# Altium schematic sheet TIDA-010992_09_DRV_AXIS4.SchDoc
size 431 x 279 mm; Date: Not shown in title block; ApprovedBy: Not shown in title block; CheckedBy: Not shown in title block; Author: Not shown in title block; CompanyName: Not shown in title block; Engineer: Not shown in title block; Organization: Not shown in title block; Address1: Not shown in title block; Address2: Not shown in title block; Address3: Not shown in title block; Address4: Not shown in title block; DocumentNumber: 9; Revision: Use project parameter SCH_Rev; SheetNumber: 9; SheetTotal: 13; PageSetup: Record=PageOptions¦CenterHorizontal=True¦CenterVertical=True¦PrintScale=1.00¦XCorrection=1.00¦YCorrection=1.00¦PrintKind=0¦BorderSize=5000000¦LeftOffset=0¦BottomOffset=0¦Orientation=2¦PaperLength=1000¦PaperWidth=1000¦Scale=100¦PaperSource=15¦PrintQuality=600¦MediaType=1¦DitherType=10¦PaperKind=Letter¦PrintScaleMode=1
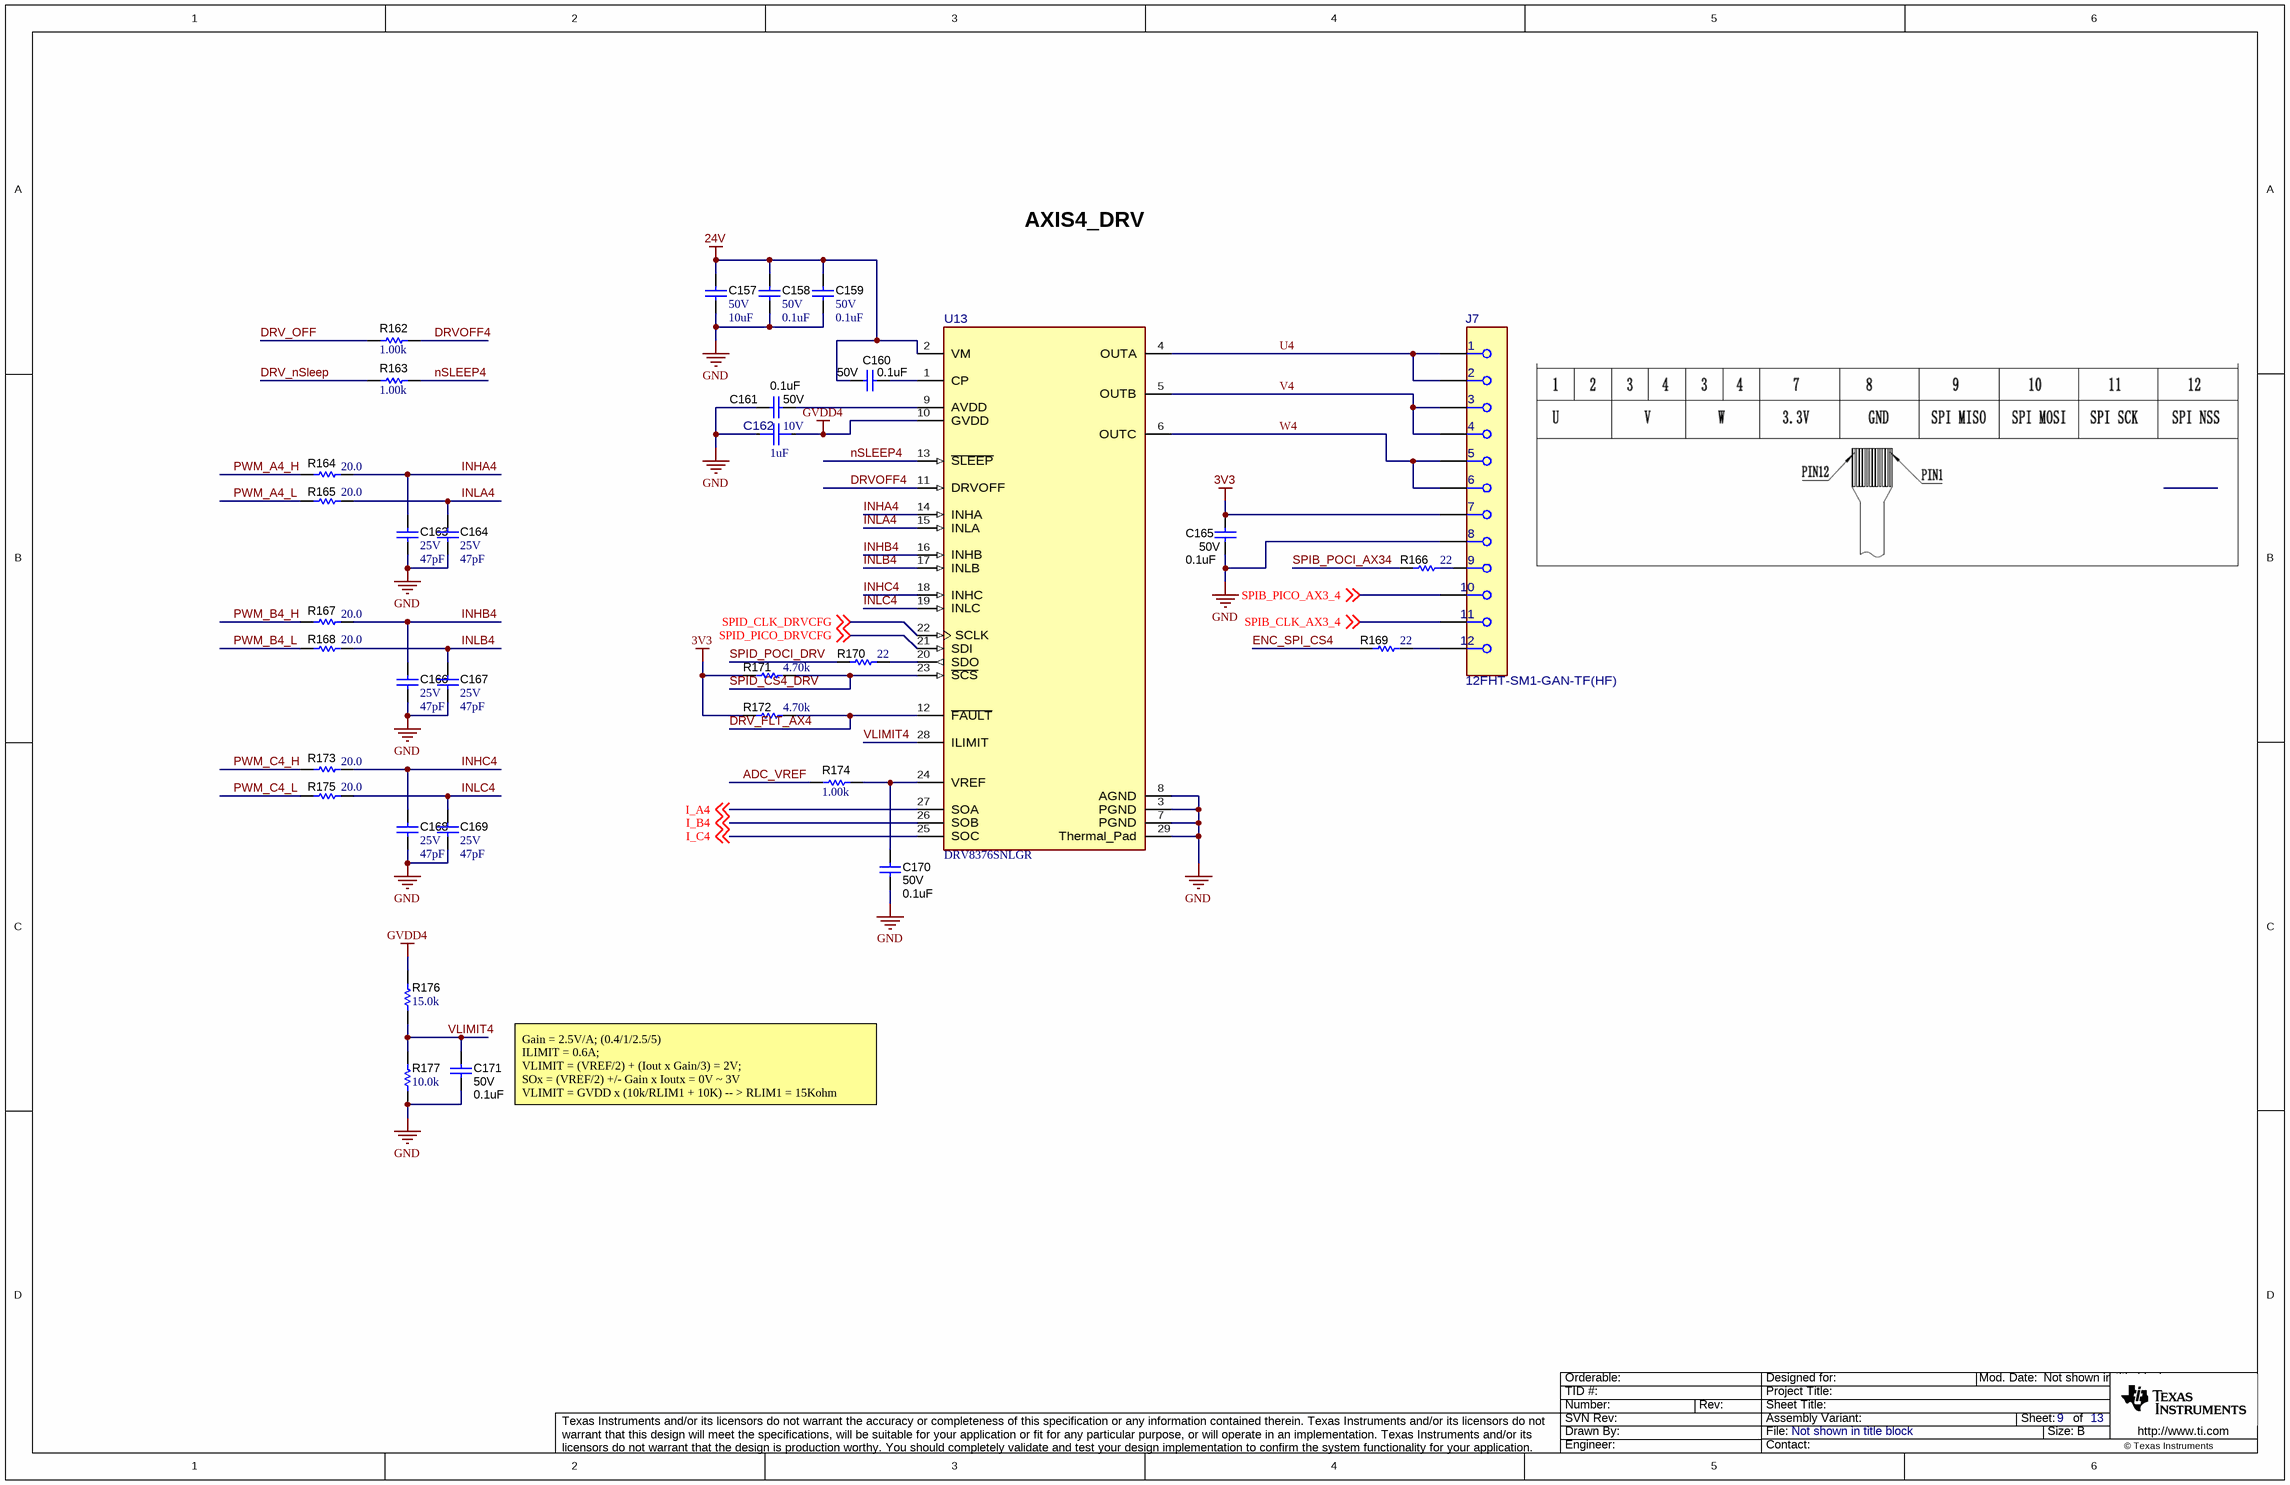
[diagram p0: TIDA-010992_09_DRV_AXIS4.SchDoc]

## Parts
C157  VDC_V: 50V  ValueDisplayed: 10uF  [1206_180]  (hidden comment: CL31B106KBHNNNE)
C158  VDC_V: 50V  ValueDisplayed: 0.1uF  [0402]  (hidden comment: C1005X7R1H104K050BE)
C159  VDC_V: 50V  ValueDisplayed: 0.1uF  [0402]  (hidden comment: C1005X7R1H104K050BE)
C160  VDC_V: 50V  ValueDisplayed: 0.1uF  [0402]  (hidden comment: CGA2B3X7R1H104M050BB)
C161  VDC_V: 50V  ValueDisplayed: 0.1uF  [0402]  (hidden comment: CGA2B3X7R1H104M050BB)
C162  VDC_V: 10V  ValueDisplayed: 1uF  [FP-GMC04X7R105K10NT_0402-MFG]  (hidden comment: GMC04X7R105K10NT)
C163  VDC_V: 25V  ValueDisplayed: 47pF  [0201_033]  (hidden comment: GRM0335C1E470JA01D)
C164  VDC_V: 25V  ValueDisplayed: 47pF  [0201_033]  (hidden comment: GRM0335C1E470JA01D)
C165  VDC_V: 50V  ValueDisplayed: 0.1uF  [0402]  (hidden comment: CGA2B3X7R1H104M050BB)
C166  VDC_V: 25V  ValueDisplayed: 47pF  [0201_033]  (hidden comment: GRM0335C1E470JA01D)
C167  VDC_V: 25V  ValueDisplayed: 47pF  [0201_033]  (hidden comment: GRM0335C1E470JA01D)
C168  VDC_V: 25V  ValueDisplayed: 47pF  [0201_033]  (hidden comment: GRM0335C1E470JA01D)
C169  VDC_V: 25V  ValueDisplayed: 47pF  [0201_033]  (hidden comment: GRM0335C1E470JA01D)
C170  VDC_V: 50V  ValueDisplayed: 0.1uF  [0402]  (hidden comment: CGA2B3X7R1H104M050BB)
C171  VDC_V: 50V  ValueDisplayed: 0.1uF  [0402]  (hidden comment: CGA2B3X7R1H104M050BB)
J7  12FHT-SM1-GAN-TF(HF)  [FP-12FHT-SM1-GAN-TF(HF)_CONN_FPC_12-MFG]
R162  ValueDisplayed: 1.00k  [0402]  (hidden comment: CRCW04021K00FKED)
R163  ValueDisplayed: 1.00k  [0402]  (hidden comment: CRCW04021K00FKED)
R164  ValueDisplayed: 20.0  [0201_033]  (hidden comment: CRCW020120R0FNED)
R165  ValueDisplayed: 20.0  [0201_033]  (hidden comment: CRCW020120R0FNED)
R166  ValueDisplayed: 22  [0201]  (hidden comment: ERJ-1GNJ220C)
R167  ValueDisplayed: 20.0  [0201_033]  (hidden comment: CRCW020120R0FNED)
R168  ValueDisplayed: 20.0  [0201_033]  (hidden comment: CRCW020120R0FNED)
R169  ValueDisplayed: 22  [0201]  (hidden comment: ERJ-1GNJ220C)
R170  ValueDisplayed: 22  [0201]  (hidden comment: ERJ-1GNJ220C)
R171  ValueDisplayed: 4.70k  [0201]  (hidden comment: RC0201FR-7D4K7L)
R172  ValueDisplayed: 4.70k  [0201]  (hidden comment: RC0201FR-7D4K7L)
R173  ValueDisplayed: 20.0  [0201_033]  (hidden comment: CRCW020120R0FNED)
R174  ValueDisplayed: 1.00k  [0402]  (hidden comment: CRCW04021K00FKED)
R175  ValueDisplayed: 20.0  [0201_033]  (hidden comment: CRCW020120R0FNED)
R176  ValueDisplayed: 15.0k  [0402]  (hidden comment: RC0402FR-0715KL)
R177  ValueDisplayed: 10.0k  [0402L]  (hidden comment: CRCW040210K0FKED)
U13  DRV8376SNLGR  [NLG0028A-MFG]

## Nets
3V3: C165.2 J7.7 R171.2 R172.2
24V: C157.1 C158.1 C159.1 C160.1 U13.2(VM)
GND: C157.2 C158.2 C159.2 C161.1 C162.1 C163.2 C164.2 C165.1 C166.2 C167.2 C168.2 C169.2 C170.1 C171.1 J7.8 R177.1 U13.3(PGND) U13.7(PGND) U13.8(AGND) U13.29(Thermal_Pad)
GVDD4: C162.2 R176.2 U13.10(GVDD)
ADC_VREF: R174.1
DRV_FLT_AX4: R172.1 U13.12(~{FAULT})
DRV_nSleep: R163.1
DRV_OFF: R162.1
DRVOFF4: R162.2 U13.11(DRVOFF)
ENC_SPI_CS4: R169.1
I_A4: U13.27(SOA) ; off-sheet I_A4
I_B4: U13.26(SOB) ; off-sheet I_B4
I_C4: U13.25(SOC) ; off-sheet I_C4
INHA4: C163.1 R164.2 U13.14(INHA)
INHB4: C166.1 R167.2 U13.16(INHB)
INHC4: C168.1 R173.2 U13.18(INHC)
INLA4: C164.1 R165.2 U13.15(INLA)
INLB4: C167.1 R168.2 U13.17(INLB)
INLC4: C169.1 R175.2 U13.19(INLC)
nSLEEP4: R163.2 U13.13(~{SLEEP})
PWM_A4_H: R164.1
PWM_A4_L: R165.1
PWM_B4_H: R167.1
PWM_B4_L: R168.1
PWM_C4_H: R173.1
PWM_C4_L: R175.1
SPIB_CLK_AX3_4: J7.11 ; off-sheet SPIB_CLK_AX3_4
SPIB_PICO_AX3_4: J7.10 ; off-sheet SPIB_PICO_AX3_4
SPIB_POCI_AX34: R166.1
SPID_CLK_DRVCFG: U13.22(SCLK) ; off-sheet SPID_CLK_DRVCFG
SPID_CS4_DRV: R171.1 U13.23(~{SCS})
SPID_PICO_DRVCFG: U13.21(SDI) ; off-sheet SPID_PICO_DRVCFG
SPID_POCI_DRV: R170.1
U4: J7.1 J7.2 U13.4(OUTA)
V4: J7.3 J7.4 U13.5(OUTB)
VLIMIT4: C171.2 R176.1 R177.2 U13.28(ILIMIT)
W4: J7.5 J7.6 U13.6(OUTC)
NetC160_2: C160.2 U13.1(CP)
NetC161_2: C161.2 U13.9(AVDD)
NetC170_2: C170.2 R174.2 U13.24(VREF)
NetJ7_9: J7.9 R166.2
NetJ7_12: J7.12 R169.2
NetR170_2: R170.2 U13.20(SDO)

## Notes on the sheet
- AXIS4_DRV
- Gain = 2.5V/A; (0.4/1/2.5/5)
  ILIMIT = 0.6A;
  VLIMIT = (VREF/2) + (Iout x Gain/3) = 2V;
  SOx = (VREF/2) +/- Gain x Ioutx = 0V ~ 3V
  VLIMIT = GVDD x (10k/RLIM1 + 10K) -- > RLIM1 = 15Kohm

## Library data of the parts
C157 = CMP-0008802-2: CAP, CERM, 10 uF, 50 V, +/- 10%, X7R, 1206; Manufacturer: Samsung; TaMin_C: -55°C; Polarized: N; SizeAreaWB_mm2: 10.92; Value1: Unknown; U/M: EA; Value: 10uF; TaMax_C: 125°C; SizeZ_mm: 1.8; SizeX_mm: 3.2; SizeY_mm: 1.6; Cap_Case: 1206; SizeArea_mm2: 5.12; Cap_F: 10µF; AEC Category: Q200
C158 C159 = CMP-0064946-2: CAP, CERM, 0.1 uF, 50 V,+/- 10%, X7R, 0402; Manufacturer: TDK; TaMin_C: -55°C; Polarized: N; SizeAreaWB_mm2: 3; Value1: Unknown; U/M: EA; Value: 0.1uF; TaMax_C: 125°C; SizeZ_mm: 0.6; SizeX_mm: 1; SizeY_mm: 0.5; Cap_F: 100nF; AEC Category: Q200
C160 C161 C165 C170 C171 = CMP-0006326-2: CAP, CERM, 0.1 uF, 50 V, +/- 20%, X7R, AEC-Q200 Grade 1, 0402; Manufacturer: TDK; TaMin_C: -55°C; Polarized: N; SizeAreaWB_mm2: 3; Value1: Unknown; U/M: EA; Value: 0.1uF; TaMax_C: 125°C; SizeZ_mm: 0.6; SizeX_mm: 1; SizeY_mm: 0.5; AEC Qualified: Y; Cap_F: 100nF; AEC Category: Q200
C162 = CMP-0093200-1: 1µF ±10% 10V Ceramic Capacitor X7R 0402 (1005 Metric); Manufacturer: Cal-Chip Electronics; TempCo: 15%; SizeZ_mm: 0.6mm; AEC Qualified: No
C163 C164 C166-C169 = CMP-0009662-3: CAP, CERM, 47 pF, 25 V, +/- 5%, C0G/NP0, 0201; Manufacturer: MuRata; TaMin_C: -55°C; Polarized: N; SizeAreaWB_mm2: 2.08; Value1: Unknown; U/M: EA; Value: 47pF; TaMax_C: 125°C; SizeZ_mm: 0.33; SizeX_mm: 0.6; SizeY_mm: 0.3; Cap_Case: 0201; SizeArea_mm2: 0.18; AEC Category: Q200
J7 = CMP-0126588-1: Conn FPC Connector F 12 POS 0.5mm Solder Ver SMD T/R; Manufacturer: JST; ContactFinish: Gold,Nickel; Current_A: 500mA; Voltage_V: 50V; AEC Qualified: No; Conn Gender: Female; Conn Orientation: Vertical; Is Female: yes; SizeZ_mm: 3.3mm; Standoff Height: 0.13mm
R162 R163 R174 = CMP-0026071-3: RES, 1.00 k, 1%, 0.063 W, AEC-Q200 Grade 0, 0402; Manufacturer: Vishay-Dale; Power_W: 63mW; TempCo: 100 ppm/C; Value_Code: 1k00; Value: 1.00k; EIA_Code: E96; Res_ohm: 1k; SizeX_mm: 1; SizeY_mm: 0.5; SizeZ_mm: 0.6; Value2: 0.063W; AEC Qualified: Y; VDC_V: 50V; AEC Category: Q200; AEC Grade: 0
R164 R165 R167 R168 R173 R175 = CMP-0078192-1: RES, 20.0, 1%, 0.05 W, 0201; Manufacturer: Vishay-Dale; Value_Code: 20R0; SizeArea_mm2: 0.18; AEC Qualified: N; AEC Category: Q200; Res_ohm: 20; Value: 20.0; SizeZ_mm: 0.33; EIA_Code: E96; TempCo: 200 ppm/C; Power_W: 50mW; VDC_V: 30V; SizeY_mm: 0.3; Value2: 0.05W; U/M: EA; SizeX_mm: 0.6
R166 R169 R170 = CMP-0027015-3: RES, 22, 5%, 0.05 W, AEC-Q200 Grade 1, 0201; Manufacturer: Panasonic; Power_W: 50mW; TempCo: 200 ppm/C; Value_Code: 22R0; U/M: EA; Value: 22; EIA_Code: E24; SizeX_mm: 0.6; SizeY_mm: 0.3; SizeZ_mm: 0.26; Value2: 0.05W; SizeArea_mm2: 0.18; AEC Qualified: Y; AEC Grade: 1; AEC Category: Q200
R171 R172 = CMP-0028031-1: RES, 4.70 k, 1%, 0.05 W, 0201; Manufacturer: Yageo America; Power_W: 50mW; TempCo: 200 ppm/C; Value_Code: 4k70; U/M: EA; Value: 4.70k; Res_ohm: 4.7k; SizeX_mm: 0.6; SizeY_mm: 0.3; SizeZ_mm: 0.26; Value2: 0.05W; SizeArea_mm2: 0.18; AEC Qualified: N; VDC_V: 25V; AEC Category: Q200
R176 = CMP-0078583-1: RES, 15.0 k, 1%, 0.063 W, 0402; Manufacturer: Yageo America; Power_W: 63mW; Green_Lifecycle: Active; TempCo: 100 ppm/C; Value_Code: 15k0; Green_REACh: Passed; Value: 15.0k; EIA_Code: E96; Res_ohm: 15k; SizeX_mm: 1; SizeY_mm: 0.5; SizeZ_mm: 0.6; Value2: 0.063W; AEC Qualified: N; AEC Category: Q200
R177 = CMP-0025958-3: RES, 10.0 k, 1%, 0.063 W, AEC-Q200 Grade 0, 0402; Manufacturer: Vishay-Dale; Power_W: 63mW; TempCo: 100 ppm/C; Value_Code: 10k0; Value: 10.0k; EIA_Code: E96; Res_ohm: 10k; SizeX_mm: 1; SizeY_mm: 0.5; SizeZ_mm: 0.6; Value2: 0.063W; AEC Qualified: Y; VDC_V: 50V; AEC Category: Q200; AEC Grade: 0
U13 = CMP-0122073-1: Three-Phase Integrated FET Motor Driver; Manufacturer: Texas Instruments; SizeZ_mm: 1mm; AEC Qualified: No; Max Supply Voltage: 65V; Min Supply Voltage: 4.5V; Motor Type: Brushless DC; Nominal Supply Current: 6.6-8.2mA; Number Of Outputs: 3; Standoff Height: 0mm; Switching Frequency: 100kHz; TaMax_C: +125°C; TaMin_C: -40°C; TJmax_C: +150°C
